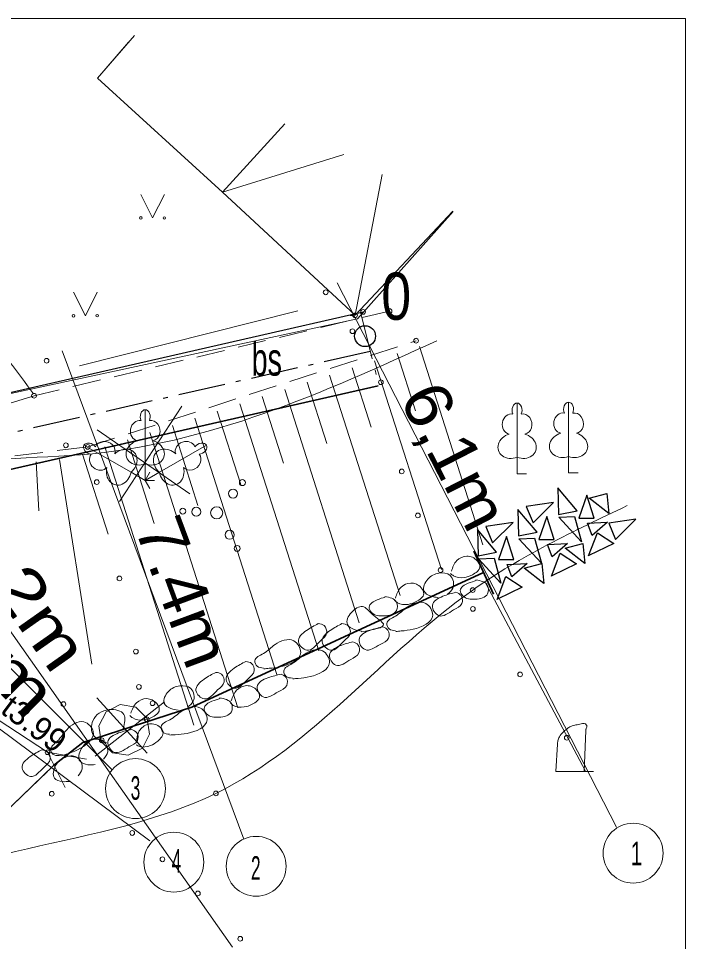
# Model space of a CAD drawing. Extents: x -1271.1 to -1218.8, y 769 to 838.3.
# Drawn here: x -1232.98 to -1218.85, y 818.71 to 838.28 of the extents above; entities that cross this region are included whole.
import ezdxf
from ezdxf.enums import TextEntityAlignment as Align

# ---------------------------------------------------------------- set-up
doc = ezdxf.new("R2010")
doc.units = 0
doc.header["$LTSCALE"] = 0.2
for name, pattern in [('DOT_DASHED', [7.7, 5, -1.2, 0.3, -1.2]), ('DOTTED', [1.5, 0.3, -1.2]), ('MEDIUM_DASHED', [4.5, 3, -1.5])]:
    doc.linetypes.add(name, pattern=pattern)
for name, color, linetype, lineweight in [('1', 7, 'Continuous', 13), ('19', 7, 'Continuous', 13), ('2', 7, 'Continuous', 13), ('28', 7, 'Continuous', 13), ('3', 7, 'Continuous', 13), ('35', 7, 'Continuous', 25), ('5', 7, 'Continuous', 13), ('55', 7, 'Continuous', 13), ('56', 7, 'Continuous', 13), ('57', 7, 'DOTTED', 13), ('6', 7, 'Continuous', 13), ('60', 7, 'Continuous', 13), ('61', 7, 'Continuous', 13), ('62', 7, 'Continuous', 13), ('63', 7, 'Continuous', 13)]:
    doc.layers.add(name, color=color, linetype=linetype, lineweight=lineweight)
doc.layers.add('10', color=7, linetype='Continuous')
doc.layers.add('11', color=7, linetype='Continuous')

msp = doc.modelspace()

# ---------------------------------------------------------------- linework, layer by layer
at = {"layer": '1'}
for p, q in [((-1226.227, 832.675), (-1220.306, 821.135)), ((-1232.058, 831.234), (-1228.211, 820.884)), ((-1224.96, 831.174), (-1224.572, 829.962)), ((-1224.484, 831.326), (-1223.14, 827.122)), ((-1225.436, 831.022), (-1224.021, 826.594)), ((-1225.913, 830.87), (-1225.512, 829.616)), ((-1226.389, 830.717), (-1224.895, 826.044)), ((-1227.341, 830.413), (-1225.76, 825.465)), ((-1226.865, 830.565), (-1226.449, 829.265)), ((-1238.894, 830.226), (-1231.002, 822.353)), ((-1227.818, 830.261), (-1227.368, 828.853)), ((-1228.446, 818.593), (-1236.594, 830.173)), ((-1228.294, 830.108), (-1226.621, 824.876)), ((-1229.246, 829.804), (-1227.509, 824.369)), ((-1228.77, 829.956), (-1228.273, 828.401)), ((-1229.723, 829.652), (-1229.18, 827.954)), ((-1230.199, 829.499), (-1228.335, 823.668)), ((-1230.675, 829.347), (-1230.107, 827.57)), ((-1231.628, 829.043), (-1231.086, 827.349)), ((-1231.151, 829.195), (-1229.267, 823.3)), ((-1232.611, 828.877), (-1232.555, 827.84)), ((-1232.113, 828.927), (-1231.432, 824.592)), ((-1239.581, 827.819), (-1230.198, 820.844))]:
    msp.add_line(p, q, dxfattribs=at)
for centre in [(-1230.5042, 821.9521), (-1219.9565, 820.5841), (-1229.691, 820.3937), (-1227.9469, 820.3057)]:
    msp.add_circle(centre, 0.635, dxfattribs=at)
msp.add_spline([(-1235.871, 827.931), (-1235.167, 828.433), (-1231.672, 829.028), (-1224.12, 831.442)], degree=3, dxfattribs=at)
at = {"layer": '19'}
msp.add_spline([(-1253.457, 785.393), (-1253.726, 794.104), (-1251.637, 801.373), (-1250.122, 804.26), (-1247.608, 807.348), (-1239.437, 815.545), (-1236.508, 819.221), (-1228.799, 821.851), (-1223.357, 826.161), (-1220.079, 827.95)], degree=3, dxfattribs=at)
at = {"layer": '2'}
msp.add_line((-1231.313, 837.008), (-1230.526, 837.915), dxfattribs=at)
msp.add_lwpolyline([(-1228.66, 834.592), (-1231.313, 837.008), (-1230.65, 837.772)], dxfattribs=at)
at = {"layer": '28'}
msp.add_lwpolyline([(-1231.544, 822.573), (-1232.369, 822.724), (-1231.995, 821.974)], dxfattribs=at)
at = {"layer": '3'}
msp.add_line((-1232.369, 822.724), (-1246.052, 831.654), dxfattribs=at)
at = {"layer": '35'}
for p, q in [((-1228.03, 831.521), (-1225.679, 832.058)), ((-1225.955, 831.988), (-1225.9, 831.986))]:
    msp.add_line(p, q, dxfattribs=at)
msp.add_lwpolyline([(-1264.692, 791.666), (-1263.121, 794.463), (-1262.995, 800.82), (-1256.407, 807.512), (-1249.819, 814.203), (-1245.888, 819.015), (-1242.275, 823.687), (-1240.604, 825.846), (-1237.968, 829.25), (-1236.511, 829.583), (-1228.03, 831.521)], dxfattribs=at)
at = {"layer": '35', "lineweight": 35}
msp.add_lwpolyline([(-1225.362, 830.487), (-1237.056, 827.834), (-1243.981, 818.809), (-1250.833, 810.905), (-1258.147, 803.474), (-1260.339, 800.099), (-1261.472, 796.156), (-1261.529, 794.093), (-1263.29, 790.894)], dxfattribs=at)
at = {"layer": '5'}
for p, q in [((-1222.416, 830.125), (-1222.416, 828.972)), ((-1221.324, 830.144), (-1221.324, 828.991)), ((-1230.298, 829.984), (-1230.298, 828.831)), ((-1222.326, 829.893), (-1222.327, 829.894)), ((-1221.234, 829.912), (-1221.235, 829.913)), ((-1230.208, 829.752), (-1230.209, 829.753)), ((-1231.597, 829.234), (-1230.599, 828.658)), ((-1228.999, 829.234), (-1229.998, 828.658)), ((-1231.351, 829.196), (-1231.352, 829.195)), ((-1229.155, 829.04), (-1229.155, 829.042)), ((-1230.298, 828.831), (-1230.298, 828.484)), ((-1222.416, 828.972), (-1222.416, 828.625)), ((-1221.324, 828.991), (-1221.324, 828.644)), ((-1230.599, 828.658), (-1230.298, 828.484)), ((-1229.998, 828.658), (-1230.298, 828.484)), ((-1230.298, 828.484), (-1230.198, 828.657)), ((-1221.324, 828.644), (-1221.124, 828.644)), ((-1230.298, 828.484), (-1230.098, 828.484)), ((-1230.298, 828.484), (-1230.198, 828.311)), ((-1222.416, 828.625), (-1222.216, 828.625)), ((-1220.993, 822.318), (-1220.959, 823.183)), ((-1220.993, 822.318), (-1221.593, 822.318)), ((-1220.993, 822.318), (-1220.793, 822.318))]:
    msp.add_line(p, q, dxfattribs=at)
for points in [[(-1230.391, 834.549), (-1230.141, 834.049), (-1229.891, 834.549)], [(-1231.817, 832.476), (-1231.567, 831.976), (-1231.317, 832.476)], [(-1221.562, 822.891), (-1221.593, 822.318), (-1221.293, 822.318), (-1220.993, 822.318)]]:
    msp.add_lwpolyline(points, dxfattribs=at)
for centre, radius in [((-1230.3911, 834.0488), 0.028), ((-1229.8911, 834.0488), 0.0263), ((-1231.8169, 831.9756), 0.028), ((-1231.3169, 831.9756), 0.0263), ((-1228.239, 828.4385), 0.064), ((-1228.4355, 828.2068), 0.096), ((-1229.5014, 827.8334), 0.064), ((-1229.217, 827.8199), 0.096), ((-1228.783, 827.7992), 0.128), ((-1228.5066, 827.3323), 0.096), ((-1228.3491, 827.043), 0.064)]:
    msp.add_circle(centre, radius, dxfattribs=at)
for centre, major_axis, ratio, start_param, end_param in [((-1222.4156, 829.9752), (0, -0.1499), 0.707107, 3.1453698, 5.2874846), ((-1222.4165, 829.9752), (0, -0.1499), 0.707107, 0.9957007, 3.1378155), ((-1221.3236, 829.9942), (0, -0.1499), 0.707107, 3.1453698, 5.2874846), ((-1221.3245, 829.9942), (0, -0.1499), 0.707107, 0.9957007, 3.1378155), ((-1230.2976, 829.8342), (0, -0.1499), 0.707107, 3.1453698, 5.2874846), ((-1230.2985, 829.8342), (0, -0.1499), 0.707107, 0.9957007, 3.1378155), ((-1222.5443, 829.6804), (-0.0387, -0.2124), 0.861323, 3.1415927, 6.2831853), ((-1222.2878, 829.6804), (0.0387, -0.2124), 0.861323, 6.2831853, 9.424778), ((-1221.4523, 829.6994), (-0.0387, -0.2124), 0.861323, 3.1415927, 6.2831853), ((-1221.1958, 829.6994), (0.0387, -0.2124), 0.861323, 6.2831853, 9.424778), ((-1230.4263, 829.5394), (-0.0387, -0.2124), 0.861323, 3.1415927, 6.2831853), ((-1230.1698, 829.5394), (0.0387, -0.2124), 0.861323, 6.2831853, 9.424778), ((-1222.5056, 829.2181), (0.3068, 0.0951), 0.814445, 1.5707963, 4.7520146), ((-1222.3265, 829.2181), (-0.3068, 0.0951), 0.814445, 1.5311707, 4.712389), ((-1221.4136, 829.2371), (0.3068, 0.0951), 0.814445, 1.5707963, 4.7520146), ((-1221.2345, 829.2371), (-0.3068, 0.0951), 0.814445, 1.5311707, 4.712389), ((-1231.467, 829.1595), (0.1298, -0.075), 0.707107, 3.1453698, 5.2874846), ((-1231.4674, 829.1588), (0.1298, -0.075), 0.707107, 0.9957007, 3.1378155), ((-1231.1477, 829.1229), (0.2033, -0.0727), 0.861323, 6.2831853, 9.424778), ((-1230.3876, 829.0771), (0.3068, 0.0951), 0.814445, 1.5707963, 4.7520146), ((-1230.2085, 829.0771), (-0.3068, 0.0951), 0.814445, 1.5311707, 4.712389), ((-1229.4484, 829.1229), (-0.2033, -0.0727), 0.861323, 3.1415927, 6.2831853), ((-1229.1287, 829.1588), (-0.1298, -0.075), 0.707107, 3.1453698, 5.2874846), ((-1229.1291, 829.1595), (-0.1298, -0.075), 0.707107, 0.9957007, 3.1378155), ((-1231.276, 828.9006), (0.1646, -0.1397), 0.861323, 3.1415927, 6.2831853), ((-1230.7667, 828.8582), (-0.2358, -0.2182), 0.814445, 1.5311707, 4.712389), ((-1229.8294, 828.8582), (0.2358, -0.2182), 0.814445, 1.5707963, 4.7520146), ((-1229.3201, 828.9006), (-0.1646, -0.1397), 0.861323, 6.2831853, 9.424778), ((-1230.8563, 828.703), (0.071, 0.3133), 0.814445, 1.5707963, 4.7520146), ((-1229.7398, 828.703), (-0.071, 0.3133), 0.814445, 1.5311707, 4.712389)]:
    msp.add_ellipse(centre, major_axis=major_axis, ratio=ratio, start_param=start_param, end_param=end_param, dxfattribs=at)
msp.add_spline([(-1220.959, 823.183), (-1220.955, 823.214), (-1220.952, 823.225), (-1220.937, 823.287), (-1220.967, 823.322), (-1221.089, 823.316), (-1221.193, 823.298), (-1221.299, 823.259), (-1221.364, 823.215), (-1221.439, 823.151), (-1221.519, 823.053), (-1221.55, 822.964), (-1221.562, 822.89)], degree=3, dxfattribs=at)
at = {"layer": '55'}
msp.add_lwpolyline([(-1264.692, 791.666), (-1263.121, 794.463), (-1263.06, 799.299), (-1247.785, 816.834), (-1237.845, 829.32), (-1225.799, 831.912), (-1223.768, 834.184)], dxfattribs=at)
at = {"layer": '56'}
for p, q in [((-1231.127, 823.582), (-1231.28, 823.283)), ((-1230.826, 823.734), (-1231.127, 823.582)), ((-1230.494, 823.68), (-1230.826, 823.734)), ((-1230.257, 823.441), (-1230.494, 823.68)), ((-1230.206, 823.109), (-1230.257, 823.441)), ((-1231.28, 823.283), (-1231.229, 822.95)), ((-1231.229, 822.95), (-1230.992, 822.712)), ((-1230.992, 822.712), (-1230.659, 822.658))]:
    msp.add_line(p, q, dxfattribs=at)
msp.add_lwpolyline([(-1230.659, 822.658), (-1230.359, 822.81), (-1230.206, 823.109)], dxfattribs=at)
at = {"layer": '57', "linetype": 'Continuous'}
msp.add_line((-1231.69, 830.917), (-1227.066, 832.083), dxfattribs=at)
at = {"layer": '6'}
for centre in [(-1226.473, 832.4722), (-1225.85, 831.9862), (-1225.679, 832.0582), (-1225.119, 832.0742), (-1225.906, 831.6481), (-1224.557, 831.4471), (-1232.388, 831.0218), (-1225.303, 830.5652), (-1232.655, 830.2792), (-1231.979, 829.2292), (-1231.517, 829.1952), (-1224.861, 828.6752), (-1231.325, 828.4482), (-1224.519, 827.7432), (-1224.038, 826.5831), (-1230.846, 826.4072), (-1223.357, 826.1612), (-1223.353, 825.7602), (-1230.496, 824.8582), (-1222.353, 824.3741), (-1230.432, 824.1082), (-1232.032, 823.7432), (-1230.143, 823.7612), (-1230.265, 823.4212), (-1231.218, 822.9762), (-1221.362, 823.0312), (-1232.369, 822.7242), (-1232.2778, 821.8421), (-1228.799, 821.8512), (-1230.573, 821.0115), (-1229.9335, 820.4535), (-1229.1819, 819.7293), (-1228.2841, 818.7686)]:
    msp.add_circle(centre, 0.05, dxfattribs=at)
at = {"layer": '60'}
for p, q in [((-1228.66, 834.592), (-1226.086, 835.393)), ((-1225.275, 834.969), (-1225.85, 831.986)), ((-1225.85, 831.986), (-1223.781, 834.19))]:
    msp.add_line(p, q, dxfattribs=at)
msp.add_lwpolyline([(-1225.85, 831.986), (-1228.66, 834.592), (-1227.339, 836.046)], dxfattribs=at)
at = {"layer": '61'}
msp.add_lwpolyline([(-1249.819, 814.203), (-1246.581, 818.124), (-1237.968, 829.25), (-1225.679, 832.058)], dxfattribs=at)
at = {"layer": '62'}
msp.add_spline([(-1235.451, 837.447), (-1235.516, 834.318), (-1233.714, 831.689), (-1232.669, 830.321)], degree=3, dxfattribs=at)
at = {"layer": '63'}
for p, q in [((-1218.845, 838.277), (-1218.845, 768.981)), ((-1229.523, 830.062), (-1230.841, 828.035)), ((-1231.314, 829.555), (-1229.355, 828.204)), ((-1220.963, 822.323), (-1223.075, 826.297)), ((-1229.889, 823.792), (-1231.36, 822.638)), ((-1231.327, 823.876), (-1230.257, 822.705))]:
    msp.add_line(p, q, dxfattribs=at)
at = {"layer": '63', "linetype": 'DOT_DASHED'}
msp.add_line((-1225.729, 832.032), (-1225.364, 830.577), dxfattribs=at)
at = {"layer": '63', "lineweight": 35}
msp.add_line((-1223.335, 826.985), (-1222.915, 826.077), dxfattribs=at)
at = {"layer": '63'}
msp.add_lwpolyline([(-1218.845, 838.277), (-1268.854, 838.277), (-1268.854, 768.981)], dxfattribs=at)
at = {"layer": '63', "linetype": 'MEDIUM_DASHED'}
for points in [[(-1225.119, 832.074), (-1232.655, 830.279), (-1235.176, 829.494), (-1238.254, 828.059), (-1240.45, 824.627), (-1244.967, 819.561)], [(-1265.079, 785.987), (-1263.807, 789.442), (-1261.536, 795.397), (-1260.86, 799.605), (-1256.627, 805.136), (-1246.564, 815.823), (-1241.769, 821.378), (-1239.214, 823.453), (-1237.177, 827.558), (-1234.848, 828.79), (-1231.517, 829.195), (-1224.557, 831.447)]]:
    msp.add_lwpolyline(points, dxfattribs=at)
at = {"layer": '63', "linetype": 'DOT_DASHED', "lineweight": 25}
for points in [[(-1225.528, 831.218), (-1237.486, 828.505), (-1244.562, 819.283), (-1251.384, 811.414), (-1258.735, 803.946), (-1261.029, 800.414), (-1262.219, 796.272), (-1262.274, 794.295), (-1264.33, 790.56), (-1266.742, 787.222)], [(-1254.918, 786.26), (-1254.605, 794.542), (-1253.865, 797.042), (-1252.437, 799.553), (-1250.698, 801.658), (-1245.95, 807.041), (-1239.139, 814.697), (-1235.363, 819.429), (-1232.239, 822.444), (-1231.619, 822.931), (-1231.44, 822.991), (-1229.31, 823.677), (-1223.125, 826.536)]]:
    msp.add_lwpolyline(points, dxfattribs=at)
at = {"layer": '63', "lineweight": 25}
for points in [[(-1221.554, 828.327), (-1221.538, 827.765), (-1221.145, 827.842)], [(-1220.937, 828.173), (-1221.107, 827.687), (-1220.783, 827.687)], [(-1220.471, 827.784), (-1220.887, 828.108), (-1220.51, 828.209)], [(-1222.402, 827.872), (-1222.386, 827.31), (-1221.993, 827.387)], [(-1222.224, 827.934), (-1222.078, 827.587), (-1221.646, 828.019)], [(-1221.785, 827.718), (-1221.955, 827.232), (-1221.631, 827.232)], [(-1221.199, 827.718), (-1221.053, 827.186), (-1221.531, 827.703)], [(-1220.474, 827.582), (-1220.328, 827.235), (-1219.896, 827.667)], [(-1223.08, 827.51), (-1222.934, 827.163), (-1222.502, 827.595)], [(-1220.922, 827.579), (-1220.498, 827.603), (-1220.821, 827.317)], [(-1223.258, 827.448), (-1223.242, 826.886), (-1222.849, 826.963)], [(-1222.641, 827.294), (-1222.811, 826.808), (-1222.487, 826.808)], [(-1222.047, 827.263), (-1221.901, 826.731), (-1222.379, 827.248)], [(-1221.77, 827.124), (-1221.346, 827.148), (-1221.669, 826.862)], [(-1220.983, 826.723), (-1221.399, 827.047), (-1221.022, 827.148)], [(-1222.903, 826.839), (-1222.757, 826.307), (-1223.235, 826.824)], [(-1222.626, 826.7), (-1222.202, 826.724), (-1222.525, 826.438)], [(-1221.851, 826.3), (-1222.267, 826.624), (-1221.89, 826.725)]]:
    msp.add_lwpolyline(points, close=True, dxfattribs=at)
for points in [[(-1220.899, 826.888), (-1220.714, 827.374), (-1220.367, 827.15), (-1220.892, 826.896)], [(-1221.688, 826.457), (-1221.503, 826.943), (-1221.156, 826.719), (-1221.681, 826.465)], [(-1222.84, 825.961), (-1222.655, 826.447), (-1222.308, 826.223), (-1222.833, 825.969)]]:
    msp.add_lwpolyline(points, dxfattribs=at)
at = {"layer": '63', "lineweight": 35}
msp.add_lwpolyline([(-1254.918, 786.26), (-1254.605, 794.542), (-1253.865, 797.042), (-1252.437, 799.553), (-1251.568, 800.606), (-1250.698, 801.658), (-1248.324, 804.35), (-1245.95, 807.041), (-1242.544, 810.869), (-1239.139, 814.697), (-1237.251, 817.063), (-1235.363, 819.429), (-1233.801, 820.936), (-1232.239, 822.444), (-1231.619, 822.931), (-1229.31, 823.677), (-1223.125, 826.536)], dxfattribs=at)
at = {"layer": '63', "lineweight": 25}
msp.add_circle((-1225.638, 831.5434), 0.2217, dxfattribs=at)
at = {"layer": '63'}
for points in [[(-1223.808, 826.56), (-1223.693, 826.785), (-1223.482, 826.88), (-1223.262, 826.78), (-1223.205, 826.652), (-1223.364, 826.484), (-1223.536, 826.428), (-1223.764, 826.462), (-1223.825, 826.513)], [(-1223.893, 826.073), (-1223.775, 826.203), (-1223.834, 826.469), (-1224.071, 826.52), (-1224.307, 826.394), (-1224.391, 826.143), (-1224.245, 826.033), (-1224.093, 826.002)], [(-1224.996, 825.99), (-1224.88, 826.216), (-1224.67, 826.31), (-1224.45, 826.211), (-1224.393, 826.083), (-1224.552, 825.915), (-1224.723, 825.858), (-1224.952, 825.893), (-1225.013, 825.944)], [(-1223.29, 826.38), (-1223.04, 826.257), (-1223.04, 826.082), (-1223.301, 825.968), (-1223.567, 826.041), (-1223.619, 826.155), (-1223.452, 826.307), (-1223.281, 826.362)], [(-1223.713, 826.113), (-1223.989, 826.029), (-1224.211, 825.832), (-1224.078, 825.62), (-1223.761, 825.74), (-1223.587, 825.878), (-1223.604, 826.045), (-1223.713, 826.113)], [(-1225.222, 826.027), (-1224.972, 825.903), (-1224.972, 825.728), (-1225.233, 825.614), (-1225.499, 825.688), (-1225.551, 825.801), (-1225.383, 825.954), (-1225.213, 826.009)], [(-1224.992, 825.3), (-1225.127, 825.337), (-1225.176, 825.452), (-1224.994, 825.608), (-1224.746, 825.799), (-1224.353, 825.877), (-1224.205, 825.629), (-1224.616, 825.331), (-1224.872, 825.294), (-1224.986, 825.283)], [(-1225.723, 825.278), (-1225.25, 825.442), (-1225.482, 825.645), (-1225.691, 825.811), (-1225.928, 825.686), (-1226.011, 825.434), (-1225.866, 825.324), (-1225.714, 825.293)], [(-1226.63, 825.449), (-1226.879, 825.305), (-1227.05, 825.062), (-1226.872, 824.886), (-1226.591, 825.076), (-1226.453, 825.249), (-1226.508, 825.408), (-1226.63, 825.449)], [(-1226.128, 825.449), (-1226.377, 825.305), (-1226.548, 825.062), (-1226.37, 824.886), (-1226.089, 825.076), (-1225.951, 825.249), (-1226.006, 825.408), (-1226.128, 825.449)], [(-1225.259, 825.38), (-1225.537, 825.305), (-1225.765, 825.115), (-1225.639, 824.899), (-1225.318, 825.009), (-1225.14, 825.141), (-1225.152, 825.309), (-1225.259, 825.38)], [(-1227.79, 824.508), (-1227.925, 824.545), (-1227.974, 824.66), (-1227.792, 824.816), (-1227.544, 825.007), (-1227.151, 825.085), (-1227.003, 824.837), (-1227.414, 824.539), (-1227.67, 824.502), (-1227.784, 824.491)], [(-1227.179, 824.295), (-1227.313, 824.332), (-1227.362, 824.447), (-1227.18, 824.603), (-1226.932, 824.794), (-1226.539, 824.872), (-1226.391, 824.625), (-1226.802, 824.326), (-1227.058, 824.289), (-1227.172, 824.279)], [(-1225.895, 825.063), (-1226.17, 824.98), (-1226.393, 824.783), (-1226.26, 824.571), (-1225.942, 824.691), (-1225.769, 824.828), (-1225.786, 824.996), (-1225.895, 825.063)], [(-1228.165, 824.647), (-1228.414, 824.503), (-1228.585, 824.26), (-1228.407, 824.084), (-1228.126, 824.274), (-1227.988, 824.447), (-1228.043, 824.606), (-1228.165, 824.647)], [(-1228.802, 824.416), (-1229.051, 824.272), (-1229.222, 824.029), (-1229.044, 823.853), (-1228.763, 824.043), (-1228.625, 824.216), (-1228.68, 824.375), (-1228.802, 824.416)], [(-1227.418, 824.377), (-1227.696, 824.302), (-1227.924, 824.112), (-1227.798, 823.896), (-1227.477, 824.006), (-1227.299, 824.138), (-1227.311, 824.306), (-1227.418, 824.377)], [(-1229.401, 823.678), (-1229.279, 823.804), (-1229.33, 824.072), (-1229.565, 824.13), (-1229.805, 824.012), (-1229.896, 823.763), (-1229.754, 823.649), (-1229.603, 823.613)], [(-1228.475, 823.814), (-1228.36, 824.04), (-1228.15, 824.135), (-1227.929, 824.035), (-1227.873, 823.907), (-1228.031, 823.739), (-1228.203, 823.683), (-1228.431, 823.717), (-1228.493, 823.768)], [(-1230.604, 823.549), (-1230.482, 823.771), (-1230.269, 823.859), (-1230.052, 823.753), (-1229.999, 823.623), (-1230.163, 823.46), (-1230.336, 823.409), (-1230.563, 823.45), (-1230.623, 823.503)], [(-1228.721, 823.878), (-1228.471, 823.755), (-1228.472, 823.579), (-1228.732, 823.465), (-1228.999, 823.539), (-1229.05, 823.653), (-1228.883, 823.805), (-1228.712, 823.86)], [(-1230.764, 823.229), (-1230.75, 823.525), (-1231.062, 823.627), (-1231.407, 823.39), (-1231.398, 823.086), (-1231.122, 822.93)], [(-1229.784, 823.104), (-1229.917, 823.145), (-1229.963, 823.261), (-1229.776, 823.412), (-1229.522, 823.595), (-1229.127, 823.661), (-1228.987, 823.409), (-1229.407, 823.123), (-1229.664, 823.094), (-1229.778, 823.087)], [(-1232.089, 822.659), (-1232.228, 822.665), (-1232.303, 822.765), (-1232.161, 822.959), (-1231.963, 823.201), (-1231.598, 823.367), (-1231.398, 823.16), (-1231.73, 822.775), (-1231.971, 822.681), (-1232.079, 822.645)], [(-1230.583, 823.207), (-1230.861, 823.132), (-1231.089, 822.942), (-1230.963, 822.726), (-1230.642, 822.836), (-1230.464, 822.968), (-1230.476, 823.136), (-1230.583, 823.207)], [(-1230.483, 822.93), (-1230.423, 823.176), (-1230.24, 823.316), (-1230.003, 823.27), (-1229.918, 823.158), (-1230.034, 822.958), (-1230.188, 822.864), (-1230.418, 822.845), (-1230.49, 822.881)], [(-1231.179, 822.578), (-1231.094, 822.731), (-1231.213, 822.977), (-1231.455, 822.972), (-1231.656, 822.796), (-1231.68, 822.532), (-1231.513, 822.459), (-1231.358, 822.463)], [(-1232.488, 822.774), (-1232.737, 822.63), (-1232.908, 822.387), (-1232.73, 822.211), (-1232.449, 822.401), (-1232.311, 822.574), (-1232.366, 822.733), (-1232.488, 822.774)], [(-1231.72, 822.221), (-1231.635, 822.374), (-1231.754, 822.62), (-1231.996, 822.615), (-1232.197, 822.439), (-1232.221, 822.175), (-1232.054, 822.102), (-1231.899, 822.106)]]:
    msp.add_spline(points, degree=3, dxfattribs=at)

# ---------------------------------------------------------------- texts
at = {"layer": '1'}
for s, width, p in [('3', 0.55, (-1230.607, 821.716)), ('1', 0.65, (-1220.005, 820.329)), ('4', 0.55, (-1229.737, 820.17)), ('2', 0.55, (-1228.057, 820.02))]:
    msp.add_text(s, height=0.5, dxfattribs=dict(at, width=width)).set_placement(p)
at = {"layer": '10', "width": 0.65}
msp.add_text('bs', height=0.7, dxfattribs=at).set_placement((-1227.721, 830.705), align=Align.CENTER)
at = {"layer": '11'}
msp.add_text('t3.99', height=0.5, rotation=323.042, dxfattribs=at).set_placement((-1232.8003, 823.1276), align=Align.CENTER)
at = {"layer": '63', "width": 0.85}
msp.add_text('0', height=1, dxfattribs=at).set_placement((-1224.9775, 831.89), align=Align.CENTER)
at = {"layer": '63'}
for s, rotation, width, p in [('6,1m', 297.162, 1.1, (-1224.1785, 828.7723)), ('8,2m', 305.131, 1.25, (-1233.3202, 825.8562)), ('7.4m', 290.39, 1.1, (-1229.9623, 825.9537)), ('8,9m', 315.069, 1.3, (-1234.1616, 824.746))]:
    msp.add_text(s, height=1, rotation=rotation, dxfattribs=dict(at, width=width)).set_placement(p, align=Align.CENTER)

doc.saveas('drawing.dxf')
